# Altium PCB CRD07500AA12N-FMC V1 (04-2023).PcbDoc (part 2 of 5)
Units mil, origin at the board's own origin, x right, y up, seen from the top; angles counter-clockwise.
Board outline 8000 x 8000 mil, 4 copper layers (Top Layer, Layer 1, Layer 2, Bottom Layer), stack 107.988 mil thick; 393 components, 213 nets, 1142 pads, 380 vias.
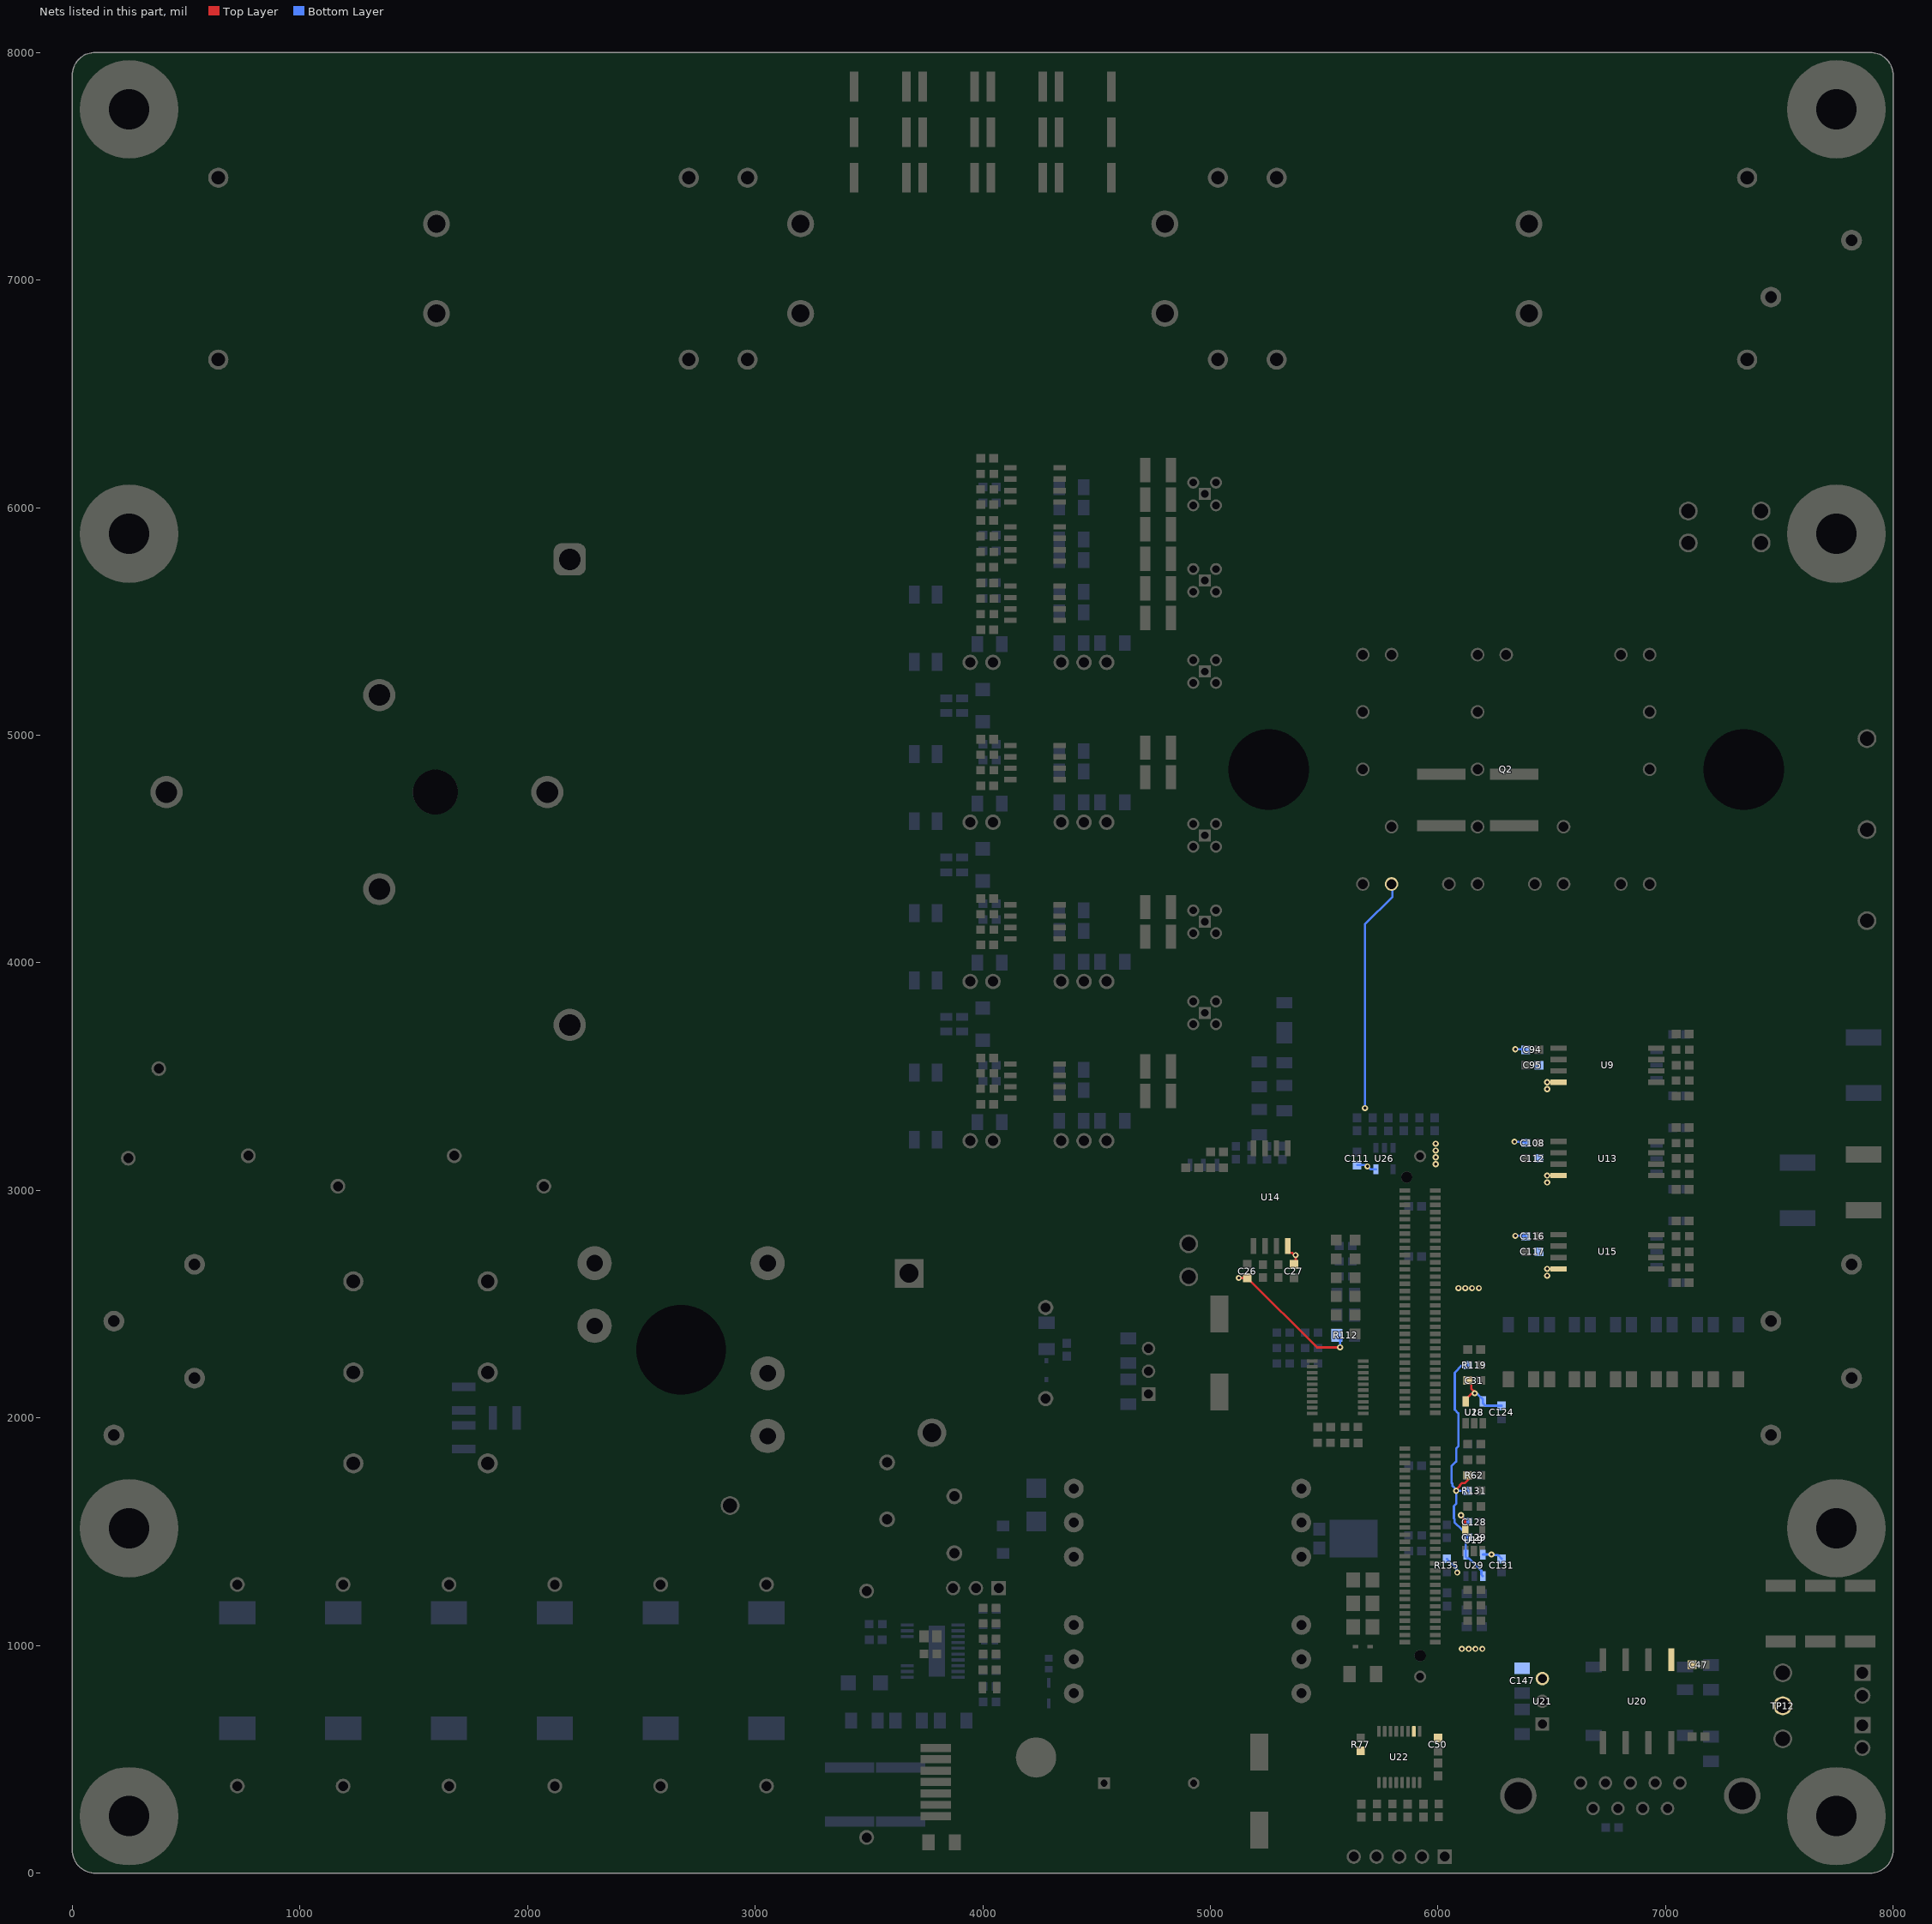
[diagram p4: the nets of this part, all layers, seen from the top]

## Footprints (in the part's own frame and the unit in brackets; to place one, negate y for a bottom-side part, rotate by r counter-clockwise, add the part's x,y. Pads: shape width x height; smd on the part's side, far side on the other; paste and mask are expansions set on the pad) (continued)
SMBJSeries_LTF [mil]
  rect 86x86 smd paste+0 mask+0: 1(-73,0) 2(73,0)
  silkscreen extent -180,-82 115,82, body extent -110,-77 110,77, height 98
SOD323_DIO [mm]
  rect 1.111x0.401 smd paste+0 mask+0: 1(-1.15,0) 2(1.15,0)
  silkscreen extent -1.03,-0.83 1.03,0.83, body extent -1.35,-0.7 1.35,0.7, height 0.81
SOT-89_4P5X2P45_DIO [mil]
  rect 21x55 smd paste+0 mask+0: 1(-59.06,-64) 2(0,-64) 3(59.06,-64)
  Top Layer region: 10.5,-48 -10.5,-48 -10.5,-27.5 -31.5,-7.5 -31.5,97.5 -16.25,97.5 16.25,97.5 31.5,97.5 31.5,-7.5 10.5,-27.5
  silkscreen extent -104,-88 94,53, body extent -92,-89 92,87, height 67
SOT_20100V_ONS [mil]
  rect 57x53 smd paste+0 mask+0: 1(41.34,-112.5) 2(-41.34,-112.5)
  rect 165x211 smd paste+0 mask+0: 3(0,39.5)
  silkscreen extent -97,-126 97,241, body extent -91,-131 91,131, height 49
TECO-640456-2_V [mm] "HDR, 2-Leads, Body 5.715x5.08mm, Pitch 2.54mm"
  rect 1.8x1.8 hole 1.3: 1(1.27,0)
  round 1.8 hole 1.3: 2(-1.27,0)
  silkscreen extent -2.54,-2.54 3.26,3.17, body extent -2.54,-2.67 2.54,3.17, height 10.09
TMDSCNCD280039C [mm]
  rect 0.5x1.2 smd paste+0 mask+0: 1(25.2,1.7) 2(25.2,-1.7) 3(24.4,1.7) 4(24.4,-1.7) 5(23.6,1.7) 6(23.6,-1.7) 7(22.8,1.7) 8(22.8,-1.7) 9(22,1.7) 10(22,-1.7) 11(21.2,1.7) 12(21.2,-1.7) 13(20.4,1.7) 14(20.4,-1.7) 15(19.6,1.7) 16(19.6,-1.7) 17(18.8,1.7) 18(18.8,-1.7) 19(18,1.7) 20(18,-1.7) 21(17.2,1.7) 22(17.2,-1.7) 23(16.4,1.7) 24(16.4,-1.7) 25(15.6,1.7) 26(15.6,-1.7) 27(14.8,1.7) 28(14.8,-1.7) 29(14,1.7) 30(14,-1.7) 31(13.2,1.7) 32(13.2,-1.7) 33(12.4,1.7) 34(12.4,-1.7) 35(11.6,1.7) 36(11.6,-1.7) 37(10.8,1.7) 38(10.8,-1.7) 39(10,1.7) 40(10,-1.7) 41(9.2,1.7) 42(9.2,-1.7) 43(8.4,1.7) 44(8.4,-1.7) 45(7.6,1.7) 46(7.6,-1.7) 47(6.8,1.7) 48(6.8,-1.7) 49(6,1.7) 50(6,-1.7) 51(5.2,1.7) 52(5.2,-1.7) 53(4.4,1.7) 54(4.4,-1.7) 55(3.6,1.7) 56(3.6,-1.7) 57(-0.4,1.7) 58(-0.4,-1.7) 59(-1.2,1.7) 60(-1.2,-1.7) 61(-2,1.7) 62(-2,-1.7) 63(-2.8,1.7) 64(-2.8,-1.7) 65(-3.6,1.7) 66(-3.6,-1.7) 67(-4.4,1.7) 68(-4.4,-1.7) 69(-5.2,1.7) 70(-5.2,-1.7) 71(-6,1.7) 72(-6,-1.7) 73(-6.8,1.7) 74(-6.8,-1.7) 75(-7.6,1.7) 76(-7.6,-1.7) 77(-8.4,1.7) 78(-8.4,-1.7) 79(-9.2,1.7) 80(-9.2,-1.7) 81(-10,1.7) 82(-10,-1.7) 83(-10.8,1.7) 84(-10.8,-1.7) 85(-11.6,1.7) 86(-11.6,-1.7) 87(-12.4,1.7) 88(-12.4,-1.7) 89(-13.2,1.7) 90(-13.2,-1.7) 91(-14,1.7) 92(-14,-1.7) 93(-14.8,1.7) 94(-14.8,-1.7) 95(-15.6,1.7) 96(-15.6,-1.7) 97(-16.4,1.7) 98(-16.4,-1.7) 99(-17.2,1.7) 100(-17.2,-1.7) 101(-18,1.7) 102(-18,-1.7) 103(-18.8,1.7) 104(-18.8,-1.7) 105(-19.6,1.7) 106(-19.6,-1.7) 107(-20.4,1.7) 108(-20.4,-1.7) 109(-21.2,1.7) 110(-21.2,-1.7) 111(-22,1.7) 112(-22,-1.7) 113(-22.8,1.7) 114(-22.8,-1.7) 115(-23.6,1.7) 116(-23.6,-1.7) 117(-24.4,1.7) 118(-24.4,-1.7) 119(-25.2,1.7) 120(-25.2,-1.7)
  round 1.34 hole 0.84 paste-1000 mask+0: 121(-29.05,0) 122(29.05,0)
  round 1.27 hole 1.27 unplated paste-1000 mask+0: ""(-26.7,-1.5) ""(26.7,0)
  silkscreen extent -33.55,-4.25 33.55,3.56, body extent -33.87,-4.89 34.67,5.68, height 57.35
TSSOP20_FE_BB(16) [mm]
  rect 1.461x0.351 smd paste+0 mask+0: 1(-2.825,2.925) 2(-2.825,2.275) 3(-2.825,1.625) 8(-2.825,-1.625) 9(-2.825,-2.275) 10(-2.825,-2.925) 11(2.825,-2.925) 12(2.825,-2.275) 13(2.825,-1.625) 14(2.825,-0.975) 15(2.825,-0.325) 16(2.825,0.325) 17(2.825,0.975) 18(2.825,1.625) 19(2.825,2.275) 20(2.825,2.925)
  rect 1.78x5.68 smd paste-2.827 mask+0: EPAD(0.47,0)
  silkscreen extent -4.06,-3.38 4.06,3.38, body extent -3.2,-3.3 3.2,3.3, height 1.2
WCAP-FTDB_L32W9H18 [mm] "Film Capacitor, THT, body 32.00x9.00mm"
  round 1.65 hole 1.1: 1(-13.75,0) 2(13.75,0)
  silkscreen extent -16.5,-5 16.5,5, body extent -16,-4.5 16,4.5, height 18
WCAP-FTDB_L57W45H65 [mm] "Film Capacitor, THT, body 57.00x45.00mm"
  round 2.25 hole 1.5: 1(-26.25,-10.15) 1(-26.25,10.15) 2(26.25,-10.15) 2(26.25,10.15)
  silkscreen extent -29,-23 29,23, body extent -28.5,-22.5 28.5,22.5, height 65
WCAP-FTXX_L26W11H20_CS [mm] "Film Capacitors, 26x11x20mm"
  round 1.65 hole 1.1: 1(-11.25,0) 2(11.25,0)
  silkscreen extent -13.25,-5.75 13.25,5.75, body extent -13,-5.5 13,5.5, height 20.05
WE-SL2 [mm] "SMD Inductor, 4-Leads, Body 6.3 x 9.5 mm"
  rect 2x1.2 smd: 1(-3.75,1.27) 2(-3.75,-1.27) 3(3.75,-1.27) 4(3.75,1.27)
  silkscreen extent -4.7,-3.18 4.7,3.18, body extent -4.6,-3 4.6,3, height 5
"WE-TPB HV_Type 4XL_744839047160" [mm] "Three-Phase Common Mode Power Line Choke, 6-Leads, body diameter 70mm"
  rrect50% 3.6x3.6 hole 2.4: 1(15,25.981)
  round 3.6 hole 2.4: 2(15,-25.981) 3(-30,0) 4(12.5,0) 5(-6.25,-10.825) 6(-6.25,10.825)
  round 5 hole 5 unplated: MH1(0,0)
  silkscreen extent -35,-35 35,35, body extent -34,-31.29 31.35,30.7, height 37.6

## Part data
C1 C2 C3 C4 C5 C6 C7 C10 C11 C12 C14 C17 C33: "CAP CER 56PF 50V C0G/NP0 0603", Capacitance=56pF, Case Code (Imperial)=0603, Case Code (Metric)=1608, Dielectric=C0G, Manufacturer=SAMSUNG, Max Operating Temperature=125°C, Min Operating Temperature=-55°C, Package Quantity=1, Temperature Coefficient=30ppm/°C, Tolerance=5%, Voltage=50V
C8 C9: "CAP FILM 2200PF 10% 1KVDC 2220", Capacitance=2.2nF, Case Code (Imperial)=2220, Case Code (Metric)=5750, Dielectric Material=Polyester, Manufacturer=KEMET, Max Operating Temperature=125°C, Min Operating Temperature=-55°C, Ratings=AEC-Q200, Tolerance=10%, Voltage Rating=1kV, Voltage Rating (AC)=250V
C13 C18 C19 C24 C26 C94 C108 C117 C143: "CAP CER 4.7UF 25V X5R 0603", Capacitance=4.7µF, Case Code (Imperial)=0603, Case Code (Metric)=1608, Dielectric=X5R, Manufacturer=SAMSUNG, Max Operating Temperature=85°C, Min Operating Temperature=-55°C, Package Quantity=1, Tolerance=20%, Voltage Rating=25V
C15 C20 C25 C110 C130: "CAP CER 4700PF 25V 10% X7R 0603", Capacitance=4.7nF, Case Code (Imperial)=0603, Case Code (Metric)=1608, Dielectric=X7R, Dielectric Material=Ceramic, Manufacturer=KEMET, Manufacturer Part Number=C0603C472K3RACTU, Max Operating Temperature=125°C, Min Operating Temperature=-55°C, Package Quantity=1, Supplier Part Number 1=67AH9250, Tolerance=10%, Voltage Rating=25V
C16 C22 C23 C27 C28 C95 C100 C109 C112 C113 C116: library part CMP-2006-03057-2, "CAP CER 0.1UF 25V X7R 0603", Capacitance=0.1μF, Manufacturer=KEMET, Package=0603, Temperature="-55°C to +125°C", Temperature Characteristic=X7R, Temperature Coefficient=30ppm/°C, Temperature Range High=+125°C, Temperature Range Low=-55°C, Tolerance=0.1, Voltage Rating=25V
C21 C93 C107 C115: "CAP CER 0.33UF 50V X7R 0603", Capacitance=330nF, Case Code (Imperial)=0603, Case Code (Metric)=1608, Dielectric=X7R, Dielectric Material=Ceramic, Manufacturer=TDK, Max Operating Temperature=125°C, Min Operating Temperature=-55°C, Package Quantity=1, Supplier Part Number 1=81AC7913, Tolerance=10%, Voltage=50V
C29 C51: library part CMP-05428-000644-1, "CAP ALUM POLY 470UF 20% 25V SMD", Capacitance=470μF, Case/Package=Radial, ESR (Equivalent Series Resistance)=20mR, Manufacturer=PANASONIC, Manufacturer Part Number=EEH-ZK1E471P, Max Operating Temperature=125°C, Min Operating Temperature=-55°C, Package=RADIAL, Ratings=AEC-Q200, Resistor Type=Hybrid, Tolerance=20%, Voltage Rating=25V
C30 C34 C35 C122 C125 C127: "CAP CER 10000PF 25V X7R 0603", Capacitance=10nF, Case Code (Imperial)=0603, Case Code (Metric)=1608, Manufacturer=SAMSUNG, Max Operating Temperature=125°C, Min Operating Temperature=-55°C, Ratings=AEC-Q200, Tolerance=10%, Voltage Rating=25V
C31: library part CMP-2006-03057-2, "CAP CER 0.1UF 25V X7R 0603", Capacitance=0.10μF, Manufacturer=KEMET, Package=0603, Temperature="-55°C to +125°C", Temperature Characteristic=X7R, Temperature Coefficient=30ppm/°C, Temperature Range High=+125°C, Temperature Range Low=-55°C, Tolerance=0.1, Voltage Rating="25 V"
C32 C65 C66 C68 C70 C72 C74 C79 C81 C86 C88 C96 C98: "CAP CER 2.2UF 50V X5R 0603", Capacitance=2.2μF, Case Code (Imperial)=0603, Case Code (Metric)=1608, Manufacturer=MURATA, Max Operating Temperature=85°C, Min Operating Temperature=-55°C, Ratings=AEC-Q200, Tolerance=20%, Voltage Rating=50V
C36: "WCAP-FTDB DC-LINK CAPACITOR (MKP", Capacitance=1µF, Insulation Resistance=10GΩ, Manufacturer=WURTH, Operating Temperature Max=105°C, Operating Temperature Min=-40°C, Package=N/A, Rate of Voltage Rise=70V/µs, Rated Voltage (DC)=900V, Supplier Part Number 1=710-890724427001CS
C37 C38 C39 C40 C41 C42: "CAP FILM 1UF 10% 310VAC RADIAL", Capacitance=1µF, Dielectric=PP, Manufacturer=WURTH, Max Operating Temperature=105°C, Min Operating Temperature=-40°C, Package=RADIAL, Ratings=X2, Supplier Part Number 1=93X5080, Tolerance=10%, Voltage Rating (AC)=310V
C43 C44 C45: library part CMP-08246-006112-1, "CAP CER 33UF 25V JB 1206", Capacitance=33μF, Case Code (Imperial)=1206, Case Code (Metric)=3216, Dielectric Material=Ceramic, Manufacturer=TDK, Max Operating Temperature=85°C, Min Operating Temperature=-25°C, Package Quantity=2000, Tolerance=20%, Voltage Rating=25V
C46: library part CMP-13271-004306-1, "CAP CER 4.7UF 50V X5R 0805", Capacitance=4.7μF, Case Code (Imperial)=0805, Case Code (Metric)=2012, Dielectric=X5R, Manufacturer=SAMSUNG, Max Operating Temperature=85°C, Min Operating Temperature=-55°C, Package Quantity=1, Tolerance=10%, Voltage Rating=50V
C47 C49 C50 C52 C105 C111 C114 C118 C119 C121 C124 C126 C128 C129 C131 C133 C141: library part CMP-2006-03057-2, "CAP CER 0.1UF 25V X7R 0603", Capacitance=0.10μF, Manufacturer=KEMET, Package=0603, Temperature="-55°C to +125°C", Temperature Characteristic=X7R, Temperature Coefficient=30ppm/°C, Temperature Range High=+125°C, Temperature Range Low=-55°C, Tolerance=0.1, Voltage Rating=25V
C48 C54 C55 C56 C148: library part CMP-2006-03341-2, "CAP CER 1000PF 100V C0G/NP0 0603", Capacitance=1nF, Manufacturer=KEMET, Package=0603, Temperature="-55°C to +125°C", Temperature Characteristic=C0G, Temperature Coefficient=30ppm/°C, Temperature Range High=+125°C, Temperature Range Low=-55°C, Tolerance=0.05, Voltage Rating=100V
C53: library part CMP-02417-000069-1, "CAP CER 2200PF 760VAC Y5U RADIAL", Capacitance=2.2nF, Case/Package=Radial, Dielectric=Y5U, Manufacturer=VISHAY, Max Operating Temperature=125°C, Min Operating Temperature=-40°C, Package=RADIAL, Package Quantity=500, Ratings=X1, Resistor Type=Ceramic, Tolerance=20%, Voltage=500V, Voltage Rating (AC)=760V
C57 C58 C59: library part 890724429010CS, "WCAP-FTDB DC-LINK CAPACITOR (MKP", Capacitance=75µF, Insulation Resistance=133.33MΩ, Manufacturer=WURTH, Operating Temperature Max=105°C, Operating Temperature Min=-40°C, Package=N/A, Rate of Voltage Rise=15V/µs, Rated Voltage (DC)=900V
C60 C61 C62 C63: "CAP ALUM 1200UF 20% 400V SNAP", Capacitance=1.2mF, Case/Package=Radial, ESR (Equivalent Series Resistance)=100mR, Manufacturer=TDK, Max Operating Temperature=85°C, Min Operating Temperature=-25°C, Package=N/A, Supplier Part Number 1=16AC3142, Tolerance=20%, Voltage Rating=400V
C64 C67 C69 C71 C73 C75 C76 C77 C78 C80 C82 C83 C84 C85 C87 C89 C90 C91 C92 C97 C99 C101 C102 C106 C120 C123 C146 C147 C149 C150: library part CMP-13271-001434-1, "CAP CER 10UF 25V X7R 1206", Capacitance=10μF, Case Code (Imperial)=1206, Case Code (Metric)=3216, Dielectric=X7R, Manufacturer=SAMSUNG, Max Operating Temperature=125°C, Min Operating Temperature=-55°C, Package Quantity=1, Tolerance=10%, Voltage Rating=25V
C103: "CAP CER 0.56UF 10V X5R 0603", Capacitance=560nF, Case Code (Imperial)=0603, Case Code (Metric)=1608, Dielectric=X5R, Dielectric Material=Ceramic, Manufacturer=KEMET, Max Operating Temperature=85°C, Min Operating Temperature=-55°C, Package Quantity=4000, Supplier Part Number 1=67AC7992, Tolerance=10%, Voltage=10V
C104: "CAP CER 1UF 10V X7R 0603", Capacitance=1μF, Case Code (Imperial)=0603, Case Code (Metric)=1608, Dielectric=X7R, Dielectric Material=Ceramic, Manufacturer=KEMET, Max Operating Temperature=125°C, Min Operating Temperature=-55°C, Package Quantity=1, Supplier Part Number 1=76Y2906, Tolerance=10%, Voltage Rating=10V
C132 C140 C142: "CAP CER 2200PF 50V X7R 0603", Capacitance=2.2nF, Case Code (Imperial)=0603, Case Code (Metric)=1608, Dielectric=X7R, Manufacturer=TDK, Max Operating Temperature=125°C, Min Operating Temperature=-55°C, Package Quantity=1, Ratings=AEC-Q200, Resistor Type=Ceramic, Supplier Part Number 1=25AC6862, Tolerance=10%, Voltage Rating=50V
C134 C135 C136 C137 C138 C139: "SMDY1 X760Y500VAC 1500PF 20% Y5U", Manufacturer=VISHAY, Package=2-SMD, Supplier Part Number 1=594-SMDY1152MY5UCR, Voltage=760V
C144 C145: library part CMP-2006-03416-2, "CAP CER 47PF 100V 10% NP0 0603", Capacitance=47pF, Manufacturer=KEMET, Package=0603, Temperature="-55°C to +125°C", Temperature Characteristic=C0G, Temperature Coefficient=30ppm/°C, Temperature Range High=+125°C, Temperature Range Low=-55°C, Tolerance=0.1, Voltage Rating=100V
C151 C152: library part CMP-08246-006150-1, "CAP CER 10000PF 2KV X7S 2220", Capacitance=10nF, Case Code (Imperial)=2220, Case Code (Metric)=5750, Dielectric=X7S, Manufacturer=TDK, Max Operating Temperature=125°C, Min Operating Temperature=-55°C, Package Quantity=1, Resistor Type=Ceramic, Tolerance=10%, Voltage Rating=2kV
D1: "BRIDGE RECT 3P 1.2KV 25A", Manufacturer="MULTICOMP PRO", Package=N/A
D2 D5 D6 D7: library part CMP-22017-000007-1, "LED GREEN CLEAR CHIP SMD", Case Code (Imperial)=0805, Case Code (Metric)=2012, Color=GREEN, Forward Current=30mA, Forward Voltage=2.1V, Illumination Color=Green, Lens Color=Colorless, Manufacturer=LITE-ON, Max Operating Temperature=85°C, Min Operating Temperature=-55°C, Package Quantity=1, Power Dissipation=100mW, Reverse Voltage=5V, Test Current=10mA
D3: "LED YELLOW CLEAR 0805 SMD", Case Code (Imperial)=0805, Case Code (Metric)=2012, Color=Yellow, Color Print=YELLOW, Forward Current=30mA, Forward Voltage=2V, Lens Color=Colorless, Manufacturer=LITE-ON, Max Operating Temperature=85°C, Max Power Dissipation=75mW, Min Operating Temperature=-55°C, Package Quantity=1, Reverse Voltage=5V, Supplier Part Number 1=6920950, Test Current=20mA
D4: "LED RED DIFFUSED 0805 SMD", Case Code (Imperial)=0805, Case Code (Metric)=2012, Color=RED, Forward Current=20mA, Forward Voltage=2V, Illumination Color=Red, Manufacturer="VISUAL COMMUNICATIONS", Max Operating Temperature=85°C, Min Operating Temperature=-40°C, Package Quantity=1, Power Rating=100mW, Reverse Voltage=5V, Supplier Part Number 1=45X6246
D8: "DIODE ZENER 13V 300MW SOD523", Manufacturer=CENTRAL, Max Operating Temperature=150°C, Max Power Dissipation=300mW, Min Operating Temperature=-65°C, Package=SOD-523, Supplier Part Number 1=1514-CMOZ13VTRPBFREECT-ND, Tolerance=5%, Zener Voltage=13V
D9 D10 D11: "3.2X1.6MM Purple SMD Led (X=0.19, Y=0.05), Rohs", Color=PURPLE, Manufacturer=Kingbright, Manufacturer Print=KINGBRIGHT, Supplier Part Number 1=604-APTR3216-VFX
D12: library part CMP-1667-00004-1, "DIODE GEN PURP 75V 150MA SOD323", Manufacturer="DIODES INC", Package=SOD-323
D13: "TVS DIODE 188VWM DO214AA", Breakdown Voltage=209V, Clamping Voltage=328V, Manufacturer=LITTELFUSE, Max Operating Temperature=150°C, Max Surge Current=2A, Mfr_Name="Littelfuse Inc", Min Operating Temperature=-55°C, Operating Supply Voltage=188V, Package=DO-214AA, Package Quantity=3000, Peak Pulse Power=600W, Power Line Protection=No, Resistor Type=Zener, Supplier Part Number 1=18-SMBJ188ACT-ND
D14: "DIODE SCHOTTKY 120V 20A TO277-3", Average Rectified Current=20A, Manufacturer=ONSEMI, Max Forward Surge Current (Ifsm)=270A, Max Repetitive Reverse Voltage (Vrrm)=120V, Package=TO-277-3
D15: "DIODE GEN PURP 1KV 1A SOD123FA", Capacitance=15pF, Forward Current=1A, Manufacturer=ONSEMI, Max Junction Temp=+150°C, Max Repetitive Reverse Voltage=1000V, Max Surge Forward Current=30A, Package=SOD-123W, Peak Reverse Current=5uA, Temperature="-55°C to +150°C", Temperature Range Low=-55°C
D16: "DIODE ZENER 220V 1.25W DO214AC", Manufacturer=VISHAY, Max Power Dissipation=1.25W, Package=DO-214AC, Tolerance=5.68%, Zener Voltage=220V
D17: "DIODE GEN PURP 150V 200MA SOD323", Average Rectified Current=200mA, Capacitance=5pF, Forward Voltage=1.25V, Manufacturer="DIODES INC", Max Forward Surge Current (Ifsm)=2.5A, Max Operating Temperature=150°C, Max Repetitive Reverse Voltage (Vrrm)=200V, Max Reverse Current=100nA, Max Reverse Voltage (DC)=150V, Mfr_Name="Diodes Inc", Min Operating Temperature=-65°C, Package=SOD-323, Package Quantity=3000, Power Dissipation=200mW, Supplier Part Number 1=4063921
F1 F2 F3: library part CMP-1502-00235-1, "FUSEHOLDER BLOCKS - PCB - CLIP C", Manufacturer=WURTH, Operating Temperature=-30to120degC, Package=N/A
HS1: "HEATSINK EXTRUSION 200MM", Case/Package=200, Manufacturer="HS MARSTON", Natural Thermal Resistance=0.7°C/W, Package=N/A, Supplier Part Number 1=526770
J1: "TERM BLK 2P SIDE ENT 6.35MM PCB", Color=Green, Current=30A, Current Rating=41A, Manufacturer="PHOENIX CONTACT", Package=N/A, Package Quantity=50, Supplier Part Number 1=651-1777545, Voltage=600V, Voltage Rating=1kV
J2 J3 J4 J5 J6 J7: "CONN MMCX JACK STR 50 OHM PCB", Manufacturer=MOLEX, Manufacturer Part Number=73415-1471, Max Frequency=6GHz, Operating Frequency=N/A, Package Quantity=500, Supplier Part Number 1=70364031
J8 J9: "TERM BLK 4P SIDE ENT 6.35MM PCB", Color=Green, Current=30A, Current Rating=41A, Manufacturer="PHOENIX CONTACT", Package=N/A, Package Quantity=50, Supplier Part Number 1=651-1777561, Voltage=600V, Voltage Rating=1kV
J10: "CONN HEADER VERT 3POS 2.54MM", Color=Black, Manufacturer=WURTH, Package=N/A, Supplier Part Number 1=20X0950
J11 J12: library part CMP-2000-05417-1, "CONN HEADER VERT 2POS 2.54MM", Color=White, Current, Rating="5 /  / A", Flammability Rating=UL94V-0, Manufacturer=TE, Package=N/A, Temperature, Operating="-55to+105 /  / degC", Voltage, Rating="250 /  / V"
J13: "CONN D-SUB PLUG 9POS R/A SLDR", Color=Black, Current Rating=5A, Manufacturer=AMPHENOL, Max Operating Temperature=155°C, Max Supply Voltage (AC)=250V, Min Operating Temperature=-55°C, Package=N/A, Supplier Part Number 1=70145033
J14: library part CMP-1502-01068-1, "CONN HEADER VERT 5POS 2.54MM", Contact Resistance=20mOhm, Manufacturer=WURTH, Operating Temperature=-40to105degC, Package=N/A, Rated Current=3A, Withstanding Voltage=500VAC, Working Voltage=250VAC
K1: library part CMP-03395-000345-1, "RELAY GEN PURPOSE SPST 30A 12V", Coil Current=75mA, Coil Power=900mW, Coil Resistance=160R, Coil Voltage (DC)=12V, Contact Current Rating=30A, Manufacturer=TE, Max Operating Temperature=105°C, Min Operating Temperature=-40°C, Package=N/A
L1: library part 744839047160, "CMC 47MH 16A 3LN TH", Case/Size Code="Type 4XL", DC Resistance Max=14mΩ, Insulation Test Voltage (AC)=3000V, Manufacturer=WURTH, Operating Temperature Max=125°C, Operating Temperature Min=-40°C, Package=N/A, Rated Current=16A, Rated Voltage (AC)=760V
L2 L3 L4 L5: "CMC 10UH 1.6A 2LN 920 OHM SMD", Case/Package=SMD/SMT, Current=1.6A, DC Resistance (DCR)=80mR, Inductance=10uH, Manufacturer=WURTH, Max Operating Temperature=125°C, Min Operating Temperature=-40°C, Package=N/A, Package Quantity=1, Supplier Part Number 1=9040408, Test Frequency=1kHz, Tolerance=30%, Voltage Rating=80V
MH1 MH2 MH3 MH4: "HEX STANDOFF M4 ALUMINUM 31MM F-F", Manufacturer=MCMASTER-CARR, Manufacturer Part Number=95947A065, Package=N/A
Q1: library part CMP-240936-000109-2, "SICFET N-CH 900V 11A D2PAK-7", Case/Package=TO-263-8, Continuous Drain Current (ID)=11A, Drain to Source Voltage (Vdss)=900V, Input Capacitance=150pF, Manufacturer=WOLFSPEED, Max Operating Temperature=150°C, Max Power Dissipation=50W, Min Operating Temperature=-55°C, Package=TO-263-7, Threshold Voltage=2.1V
Q2: "1200V SIC 6-PACK MODULE", Manufacturer=WOLFSPEED, Package=N/A
R1 R2 R3 R4 R5 R6 R7 R8 R9 R10 R11 R12: "RES 82K OHM 1% 2W 2512", Manufacturer=TE, Package=2512, Power=2W
R13 R17 R21 R25 R29 R35: "RES SMD 0 OHM JUMPER 3/4W 1210", Case Code (Imperial)=1210, Case Code (Metric)=3225, Manufacturer=VISHAY, Max Operating Temperature=155°C, Max Power Dissipation=750mW, Min Operating Temperature=-55°C, Package Quantity=10, Power Rating=0.75W, Resistance=0Ω, Supplier Part Number 1=71-CRCW12100000Z0EAH
R14 R15 R18 R19 R22 R24 R26 R27 R30 R31 R37 R39 R59: "RES SMD 49.9 OHM 1% 1/10W 0603", Case Code (Imperial)=0603, Case Code (Metric)=1608, Manufacturer=PANASONIC, Max Operating Temperature=155°C, Max Power Dissipation=100mW, Min Operating Temperature=-55°C, Package Quantity=5000, Power Rating=0.1W, Resistance=49.9Ω, Resistance Tolerance=1%, Resistor Type="Thick Film", Supplier Part Number 1=12AC1058, Temperature Coefficient=100ppm/°C, Voltage Rating=75V, Voltage Rating (DC)=50V, Working Voltage=6V
R16 R20 R23 R28 R32 R40: library part CMP-2005-02198-1, "RES 0.91 OHM 1% 1W 1210", Manufacturer=VISHAY, Package=1210, Power=1W
R33 R34 R36 R38 R41 R42 R44 R45 R46 R47 R48 R49 R50 R51: "RES 22 OHM 1% 1/10W 0603", Case Code (Imperial)=0603, Case Code (Metric)=1608, Manufacturer=YAGEO, Max Operating Temperature=155°C, Min Operating Temperature=-55°C, Power Rating=0.1W, Resistance=22Ω, Resistor Type="Thick Film", Supplier Part Number 1=3067715, Temperature Coefficient=100ppm/°C, Tolerance=1%, Voltage Rating=50V
R43 R89 R99: "RES 0.002 OHM 1% 3W 2512", Case Code (Imperial)=2512, Case Code (Metric)=6432, Manufacturer=BOURNS, Max Operating Temperature=170°C, Max Power Dissipation=3W, Min Operating Temperature=-55°C, Ratings=AEC-Q200, Resistance=2mΩ, Resistance Tolerance=1%, Resistor Type="Metal Alloy", Supplier Part Number 1=75X1531, Temperature Coefficient=75ppm/°C
R52 R63 R130 R139: "RES 0 OHM JUMPER 1/10W 0603", Case Code (Imperial)=0603, Case Code (Metric)=1608, Current Rating=1A, Manufacturer=YAGEO, Max Operating Temperature=155°C, Max Power Dissipation=100mW, Min Operating Temperature=-55°C, Package Quantity=5000, Power Rating=0.1W, Resistance=0Ω, Resistance Tolerance=1%, Resistor Type="Thick Film", Supplier Part Number 1=2581684, Temperature Coefficient=200ppm/°C, Voltage Rating=50V, Working Voltage=75V
R53 R111 R125: library part CMP-2003-04604-1, "RES 249K OHM 0.1% 1/4W 1206", Manufacturer="VISHAY DALE", Package=1206, Power=0.25W, Resistance=249kΩ
R54 R55 R56 R57 R58 R106 R107 R108 R109 R110 R120 R121 R122 R123 R124: library part CMP-2003-04604-1, "RES 249K OHM 0.1% 1/4W 1206", Manufacturer=VISHAY, Package=1206, Power=0.25W, Resistance=249kΩ
R60 R136 R137: "RES SMD 10K OHM 1% 1/10W 0603", Case Code (Imperial)=0603, Case Code (Metric)=1608, Manufacturer=PANASONIC, Manufacturer Part Number=ERJ-3EKF1002V, Max Operating Temperature=155°C, Max Power Dissipation=0.1W, Min Operating Temperature=-55°C, Package Quantity=1, Power Rating=100mW, Resistance=10kΩ, Resistance Tolerance=1%, Resistor Type="Thick Film", Supplier Part Number 1=1051156, Temperature Coefficient=100ppm/°C, Voltage Rating=75V
R61 R77 R126 R132: "RES 4.99K OHM 1% 1/10W 0603", Case Code (Imperial)=0603, Case Code (Metric)=1608, Manufacturer=YAGEO, Max Operating Temperature=155°C, Max Power Dissipation=0.1W, Min Operating Temperature=-55°C, Package Quantity=1, Resistance=4.99kΩ, Resistance Tolerance=1%, Resistor Type="Thick Film", Supplier Part Number 1=1995595, Temperature Coefficient=100ppm/°C, Voltage Rating=75V, Voltage Rating (DC)=50V
R62 R119 R131: "RES SMD 1.8K OHM 0.1% 1/5W 0603", Case Code (Imperial)=0603, Case Code (Metric)=1608, Manufacturer=PANASONIC, Max Operating Temperature=155°C, Max Power Dissipation=0.2W, Min Operating Temperature=-55°C, Resistance=1.8kΩ, Resistor Type="Thick Film", Temperature Coefficient=50ppm/°C, Tolerance=0.1%
R64 R65 R66: "RES 0 OHM JUMPER 1W 2512", Case Code (Imperial)=2512, Case Code (Metric)=6432, Manufacturer=YAGEO, Max Operating Temperature=155°C, Max Power Dissipation=1W, Min Operating Temperature=-55°C, Package Quantity=4000, Resistance=0Ω, Resistance Tolerance=5%, Resistor Type="Thick Film", Supplier Part Number 1=2465714, Temperature Coefficient=200ppm/°C, Voltage Rating=200V
R67 R68 R70: "RES SMD 20 OHM 0.1% 1/10W 0603", Case Code (Imperial)=0603, Case Code (Metric)=1608, Manufacturer=YAGEO, Max Operating Temperature=125°C, Max Power Dissipation=100mW, Min Operating Temperature=-55°C, Package Quantity=5000, Power Rating=0.1W, Resistance=20Ω, Resistor Type="Thin Film", Supplier Part Number 1=603-RT0603BRD0720RL, Temperature Coefficient=25ppm/°C, Voltage Rating=75V, Voltage Rating (DC)=50V
R69: "RES SMD 121K OHM 1% 1/10W 0603", Case Code (Imperial)=0603, Case Code (Metric)=1608, Manufacturer=YAGEO, Max Operating Temperature=125°C, Max Power Dissipation=100mW, Min Operating Temperature=-55°C, Package Quantity=5000, Power Rating=0.1W, Resistance=121kΩ, Resistor Type="Thin Film", Supplier Part Number 1=2107925, Temperature Coefficient=50ppm/°C, Tolerance=1%, Voltage Rating=75V, Voltage Rating (DC)=50V
R71: "RES 4.53K OHM 1% 1/10W 0603", Case Code (Imperial)=0603, Case Code (Metric)=1608, Manufacturer=YAGEO, Max Operating Temperature=155°C, Max Power Dissipation=100mW, Min Operating Temperature=-55°C, Package Quantity=1, Power Rating=0.1W, Resistance=4.53kΩ, Resistor Type="Thick Film", Supplier Part Number 1=3326097, Temperature Coefficient=100ppm/°C, Tolerance=1%, Voltage Rating=50V
R72: "RES SMD 44.2KOHM 0.1% 1/10W 0603", Case Code (Imperial)=0603, Case Code (Metric)=1608, Manufacturer=YAGEO, Max Operating Temperature=125°C, Max Power Dissipation=0.1W, Min Operating Temperature=-55°C, Package Quantity=5000, Power Rating=100mW, Resistance=44.2kΩ, Resistor Type="Thin Film", Temperature Coefficient=25ppm/°C, Tolerance=0.1%, Voltage Rating=75V, Voltage Rating (DC)=50V
R73 R97: "RES 10 OHM 5% 1/10W 0603", Case Code (Imperial)=0603, Case Code (Metric)=1608, Manufacturer=YAGEO, Max Operating Temperature=155°C, Max Power Dissipation=0.1W, Min Operating Temperature=-55°C, Power Rating=100mW, Resistance=10Ω, Resistance Tolerance=5%, Resistor Type="Thick Film", Supplier Part Number 1=5141098, Temperature Coefficient=200ppm/°C, Voltage Rating=50V
R74: "RES 5.6K OHM 1% 1/10W 0603", Case Code (Imperial)=0603, Case Code (Metric)=1608, Manufacturer=YAGEO, Max Operating Temperature=155°C, Min Operating Temperature=-55°C, Power Rating=0.1W, Resistance=5.6kΩ, Resistor Type="Thick Film", Supplier Part Number 1=13-RC0603FR-135K6LCT-ND, Temperature Coefficient=100ppm/°C, Tolerance=1%, Voltage Rating=50V
R75: "RES SMD 2K OHM 1% 1/4W 1206", Case Code (Imperial)=1206, Case Code (Metric)=3216, Manufacturer=YAGEO, Max Operating Temperature=125°C, Max Power Dissipation=0.25W, Min Operating Temperature=-55°C, Package Quantity=5000, Power Rating=250mW, Resistance=2kΩ, Resistor Type="Thin Film", Temperature Coefficient=50ppm/°C, Tolerance=1%, Voltage Rating=200V
R76: "RES SMD 20 OHM 1% 1/8W 0805", Case Code (Imperial)=0805, Case Code (Metric)=2012, Manufacturer=YAGEO, Max Operating Temperature=125°C, Max Power Dissipation=0.13W, Min Operating Temperature=-55°C, Package Quantity=5000, Power Rating=125mW, Resistance=20Ω, Resistor Type="Thin Film", Supplier Part Number 1=46AK6012, Temperature Coefficient=50ppm/°C, Tolerance=1%, Voltage Rating=150V
R78 R79 R80 R94 R95 R96 R133 R135: "RES SMD 1K OHM 0.5% 1/10W 0603", Case Code (Imperial)=0603, Case Code (Metric)=1608, Manufacturer=YAGEO, Max Operating Temperature=125°C, Max Power Dissipation=100mW, Min Operating Temperature=-55°C, Power Rating=0.1W, Resistance=1kΩ, Resistor Type="Thin Film", Supplier Part Number 1=6012514, Temperature Coefficient=25ppm/°C, Tolerance=0.5%, Voltage Rating=75V, Voltage Rating (DC)=50V
R81: "Res 0.05 Ohm 1.0 W 1% 1206 SMD", Manufacturer=VISHAY, Package=1206, Power=1W
R82 R83 R84 R85 R87 R88: "RES SMD 1K OHM 5% 1/8W 0805", Case Code (Imperial)=0805, Case Code (Metric)=2012, Manufacturer=VISHAY, Max Operating Temperature=155°C, Max Power Dissipation=125mW, Min Operating Temperature=-55°C, Package Quantity=5000, Power Rating=0.13W, Resistance=1kΩ, Resistor Type="Thick Film", Temperature Coefficient=200ppm/°C, Tolerance=5%, Voltage Rating=150V
R86 R90 R91 R92 R93: "THIN FILM RES SMD 68K OHM 0.1% 1", Manufacturer=VISHAY, Package=1206, Power=1W, Resistance=68kΩ, Supplier Part Number 1=71-PHPA1206E6802BST1, Tolerance=0.1%
R98: "RES SMD 20 OHM 0.1% 1/10W 0603", Case Code (Imperial)=0603, Case Code (Metric)=1608, Manufacturer=YAGEO, Max Operating Temperature=125°C, Max Power Dissipation=100mW, Min Operating Temperature=-55°C, Package Quantity=5000, Power Rating=0.1W, Resistance=20Ω, Resistor Type="Thin Film", Supplier Part Number 1=603-RT0603BRD0720RL, Temperature Coefficient=25ppm/°C, Tolerance=0.1%, Voltage Rating=75V, Voltage Rating (DC)=50V
R100 R101 R102: "RES 680 OHM 1% 1/10W 0603", Case Code (Imperial)=0603, Case Code (Metric)=1608, Manufacturer=YAGEO, Max Operating Temperature=155°C, Max Power Dissipation=100mW, Min Operating Temperature=-55°C, Package Quantity=1, Power Rating=0.1W, Resistance=680Ω, Resistance Tolerance=1%, Resistor Type="Thick Film", Supplier Part Number 1=6789788, Temperature Coefficient=100ppm/°C, Voltage Rating=50V
R103: "RES SMD 2K OHM 1% 1/8W 0805", Case Code (Imperial)=0805, Case Code (Metric)=2012, Manufacturer=YAGEO, Max Operating Temperature=125°C, Max Power Dissipation=0.13W, Min Operating Temperature=-55°C, Package Quantity=5000, Power Rating=125mW, Resistance=2kΩ, Resistor Type="Thin Film", Supplier Part Number 1=6100065, Temperature Coefficient=50ppm/°C, Tolerance=1%, Voltage Rating=150V
R104: "RES 499 OHM 1% 1/8W 0805", Case Code (Imperial)=0805, Case Code (Metric)=2012, Manufacturer=YAGEO, Max Operating Temperature=155°C, Max Power Dissipation=0.13W, Min Operating Temperature=-55°C, Package Quantity=1, Power Rating=125mW, Resistance=499Ω, Resistor Type="Thick Film", Supplier Part Number 1=5825161, Temperature Coefficient=100ppm/°C, Tolerance=1%, Voltage Rating=150V
R105: "RES 22 OHM 1% 1/4W 1206", Case Code (Imperial)=1206, Case Code (Metric)=3216, Manufacturer=STACKPOLE, Max Operating Temperature=155°C, Max Power Dissipation=0.3W, Min Operating Temperature=-55°C, Resistance=22Ω, Resistor Type="Thick Film", Temperature Coefficient=100ppm/°C, Tolerance=1%
R112: "RES 249 OHM 1% 1/8W 0805", Case Code (Imperial)=0805, Case Code (Metric)=2012, Manufacturer=YAGEO, Max Operating Temperature=155°C, Max Power Dissipation=125mW, Min Operating Temperature=-55°C, Package Quantity=1, Power Rating=0.13W, Resistance=249Ω, Resistor Type="Thick Film", Supplier Part Number 1=1233097, Temperature Coefficient=100ppm/°C, Tolerance=1%, Voltage Rating=150V
R113 R114 R115 R116 R117 R118: "RES 100K OHM 1% 1/10W 0603", Case Code (Imperial)=0603, Case Code (Metric)=1608, Manufacturer=YAGEO, Max Operating Temperature=155°C, Max Power Dissipation=100mW, Min Operating Temperature=-55°C, Power Rating=0.1W, Resistance=100kΩ, Resistance Tolerance=1%, Resistor Type="Thick Film", Supplier Part Number 1=3697448, Temperature Coefficient=100ppm/°C, Voltage Rating=50V, Working Voltage=75V
R127 R128 R129: "RES SMD 820K OHM 1% 1/3W 1210", Case Code (Imperial)=1210, Case Code (Metric)=3225, Manufacturer=ROHM, Max Operating Temperature=155°C, Max Power Dissipation=0.3W, Min Operating Temperature=-55°C, Package Quantity=4000, Resistance=820kΩ, Resistor Type="Thick Film", Supplier Part Number 1=755-KTR25JZPF8203, Temperature Coefficient=100ppm/°C, Tolerance=1%
R134: "RES 330 OHM 1% 1/10W 0603", Case Code (Imperial)=0603, Case Code (Metric)=1608, Manufacturer=YAGEO, Max Operating Temperature=155°C, Max Power Dissipation=0.1W, Min Operating Temperature=-55°C, Package Quantity=1, Power Rating=100mW, Resistance=330Ω, Resistance Tolerance=1%, Resistor Type="Thick Film", Supplier Part Number 1=2052439, Temperature Coefficient=100ppm/°C, Voltage Rating=50V
R138: "RES SMD 56.2KOHM 0.1% 1/10W 0603", Case Code (Imperial)=0603, Case Code (Metric)=1608, Manufacturer=YAGEO, Max Operating Temperature=125°C, Max Power Dissipation=100mW, Min Operating Temperature=-55°C, Package Quantity=5000, Power Rating=0.1W, Resistance=56.2kΩ, Resistor Type="Thin Film", Supplier Part Number 1=46AK5760, Temperature Coefficient=25ppm/°C, Tolerance=0.1%, Voltage Rating=75V, Voltage Rating (DC)=50V
R140: "RES SMD 100 OHM 1% 1/10W 0603", Case Code (Imperial)=0603, Case Code (Metric)=1608, Manufacturer=YAGEO, Max Operating Temperature=125°C, Max Power Dissipation=100mW, Min Operating Temperature=-55°C, Package Quantity=5000, Power Rating=0.1W, Resistance=100Ω, Resistance Tolerance=1%, Resistor Type="Thin Film", Supplier Part Number 1=4047394, Temperature Coefficient=50ppm/°C, Voltage Rating=75V
R141 R142 R143: "RES SMD 499K OHM 0.5% 1/4W 1206", Case Code (Imperial)=1206, Case Code (Metric)=3216, Manufacturer=YAGEO, Max Operating Temperature=155°C, Max Power Dissipation=0.25W, Min Operating Temperature=-55°C, Package Quantity=5000, Resistance=499kΩ, Resistor Type="Thin Film", Temperature Coefficient=25ppm/°C, Tolerance=0.5%, Voltage Rating (DC)=200V
R144: "RES SMD 120 OHM 5% 1/10W 0603", Case Code (Imperial)=0603, Case Code (Metric)=1608, Manufacturer=YAGEO, Max Operating Temperature=155°C, Max Power Dissipation=0.1W, Min Operating Temperature=-55°C, Package Quantity=1, Power Rating=100mW, Resistance=120Ω, Resistance Tolerance=5%, Resistor Type="Thick Film", Supplier Part Number 1=2424206, Temperature Coefficient=100ppm/°C, Voltage Rating=50V
RV1 RV2 RV3: library part 820525511, "DISK VARISTOR STANDARD WE-VD - B", (Reverse) Breakdown Voltage=910V, (Reverse) Peak Pulse Current=6500A, Channel Input Capacitance=430pF, Clamping Voltage=1500V, Manufacturer=WURTH, Operating Temperature Max=85°C, Operating Temperature Min=-40°C, Operating Voltage (AC)=550V, Operating Voltage (DC)=745V, Package=N/A, Power Dissipation=1W
RV4 RV5: "ICL 5 OHM 20% 20A 31MM", Current Rating=20A, Manufacturer=AMETHERM, Manufacturer Part Number=SL32-5R020-B, Package=N/A, Package Quantity=500, Resistance=5R, Supplier Part Number 1=33K3765, Tolerance=20%
T1: "TRANSFORMER FLYBACK 670UH TH", Manufacturer=SUMIDA, Package=N/A
TP1 TP3 TP8 TP12 TP13: library part CMP-1672-00002-4, "PC TEST POINT MULTIPURPOSE RED", Colour=Red, Manufacturer=KEYSTONE, Package=N/A, Package Quantity=100
TP2 TP4 TP9 TP10 TP11: library part CMP-1672-00003-4, "PC TEST POINT MULTIPURPOSE BLACK", Colour=Black, Manufacturer=KEYSTONE, Package=N/A, Package Quantity=100
TP5 TP6 TP7: library part CMP-1672-00004-4, "PC TEST POINT MULTIPURPOSE WHITE", Colour=White, Manufacturer=KEYSTONE, Package=N/A, Package Quantity=100
U1 U2 U3 U5 U7 U10: "5A/5A, 3-KVRMS SINGLE-CHANNEL IS", Manufacturer="TEXAS INSTRUMENTS", Max Operating Temperature=125°C, Mfr_Name="Texas Instruments", Min Operating Temperature=-40°C, Package=8-SOIC, Supplier Part Number 1=296-47508-ND, Working Voltage=990V
U4 U6 U8 U12: "DC DC CONVERTER 15V -3V 1.7W", Manufacturer=MURATA, Package=7-SIP, Supplier Part Number 1=580-MGJ2D121503SC
U9 U13 U14 U15: "IC ISOLATED MOD 16BIT 78K 8SOIC", Manufacturer="TEXAS INSTRUMENTS", Max Operating Temperature=125°C, Mfr_Name="Texas Instruments", Min Operating Temperature=-40°C, Package=8-SOIC, Supplier Part Number 1=296-50930-1-ND
U11: "EVAL BOARD FOR TMS320F280039C", Manufacturer="TEXAS INSTRUMENTS", Package=N/A, Supplier Part Number 1=595-TMDSCNCD280039C
U16: "DC DC CONVERTER 5V 5W", Case/Package=SIP, Current - Output 1=1A, Manufacturer=RECOM, Max Input Voltage=28V, Max Operating Temperature=85°C, Max Output Voltage=5V, Max Power Dissipation=5W, Min Input Voltage=8V, Min Operating Temperature=-40°C, Package=3-SIP, Package Quantity=42, Supplier Part Number 1=1446013
U17: library part CMP-0440-01163-3, "IC BUF NON-INVERT 5.5V 20TSSOP", F @ Nom Voltage(Max)(Mhz)=110, Generic Part Number=SN74LV541AT, ICC @ Nom Voltage(Max)(mA)=0.02, Manufacturer="TEXAS INSTRUMENTS", Operating Temperature Range(C)="-40 to 125", Package=20-TSSOP, Rating=Catalog, tpd @ Nom Voltage(Max)(ns)=7.9, Voltage(Nom)(V)=5
U18 U19 U28: library part CMP-0384-02059-2, "IC OPAMP GP 1 CIRCUIT TSOT23-5", Amplifiers Per Package=1, Generic Part Number=AD8615, Input Bias Current=200fA, Input Offset Voltage=80uV, Manufacturer="ANALOG DEVICES", Package=TSOT-23-5
U20: "IC TXRX/ISO HALF 1/1 8SOP", Drivers Per Package=1, Manufacturer="TEXAS INSTRUMENTS", Package=8-SOP, Rating=Catalog
U21: "DC DC CONVERTER 3.3V 3W", Case/Package=SIP, Manufacturer=RECOM, Max Input Voltage=28V, Max Operating Temperature=85°C, Max Output Current=1A, Max Output Power=3.3W, Max Output Voltage=3.3V, Max Power Dissipation=3W, Min Input Voltage=8V, Min Input Voltage (DC)=7V, Min Operating Temperature=-40°C, Package=3-SIP, Supplier Part Number 1=9176626
U22: library part CMP-2000-07336-1, "IC TRANSLATOR BIDIR 16TSSOP", Manufacturer="TEXAS INSTRUMENTS", Operating Temperature=-40°C~85°C, Package=16-TSSOP, Package / Case="16-TSSOP(0.173\",4.40mmWidth)", Package Description="16-Pin Small Outline Package Integrated Circuit, Body 5 x 4.4 mm, Pitch 0.65 mm", Package Reference=PW16, Standard Package=1, Voltage - Supply=1.2V~3.6V,1.65V~5.5V
U23 U24 U25 U27: "IC REG LINEAR 5V 100MA SOT89-3", Case/Package=SOT-89-3, Dropout Voltage=1.8V, Manufacturer="DIODES INC", Max Input Voltage=30V, Max Operating Temperature=125°C, Max Output Current=100mA, Max Power Dissipation=750mW, Min Operating Temperature=-40°C, Output Voltage=5V, Package=TO-243AA, Package Quantity=1000, Quiescent Current=3mA, Supplier Part Number 1=1050402
U26 U29: library part CMP-0384-01498-2, "IC OPAMP GP 1 CIRCUIT SOT23-5", Amplifiers Per Package=1, Generic Part Number=AD8541, Input Bias Current=4pA, Input Offset Voltage=1mV, Manufacturer="ANALOG DEVICES", Package=SOT-23-5
U30: "600VIN MICROPOWER, ISOLATED NO-O", Manufacturer="ANALOG DEVICES", Package=20-TSSOP
U31: library part CMP-29842-000014-1, "DC DC CONVERTER 5V 1W", Case/Package=SMD/SMT, Current - Output 1=200mA, Isolation Voltage=1kV, Manufacturer=RECOM, Max Input Voltage=5.5V, Max Operating Temperature=85°C, Max Output Power=1W, Max Output Voltage=5V, Min Input Voltage=4.5V, Min Operating Temperature=-40°C, Package=8-SMD, Package Quantity=1

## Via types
v1: diameter 27, hole 13, Top Layer to Bottom Layer, tented both sides, 367 vias
v2: diameter 50, hole 28, Top Layer to Bottom Layer, tented both sides, 13 vias

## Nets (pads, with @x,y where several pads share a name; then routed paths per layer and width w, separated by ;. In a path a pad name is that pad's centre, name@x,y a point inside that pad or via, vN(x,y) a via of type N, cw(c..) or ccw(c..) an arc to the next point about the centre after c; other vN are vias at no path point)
+1.65V: C129.1 R62.2 R119.2 R131.2 U29.1 U29.4 | length 1217.2
  Top Layer w10: v1(6080,1680) 6080,1684.6 6096.61,1701.21 6096.61,1705.08 6105.4,1713.86 6118.86,1713.86 6135,1730 6135,1744.38 R62.2@6131.38,1748
  Bottom Layer w10: v1@6082.35,1682.35 6084.69,1680 R131.2@6131.38,1680 ; R119.2@6131.38,2232 6129.38,2230 6105,2230 6073.82,2198.82 6073.82,2036.09 6090,2019.91 6090,1875 6080,1865 6080,1808.67 6060.52,1789.19 6060.52,1714.48 6063.81,1711.19 6063.81,1700.79 6080,1684.6 v1(6080,1680) 6080,1622.58 6070,1612.58 6070,1558.65 6072.96,1555.7 6072.96,1541.58 6105.4,1509.14 6115.86,1509.14 6122,1503 6122,1484.43 C129.1@6131.42,1475 6122.6,1466.18 U29.4@6122.6,1399.24 6122.6,1389.4 6129.41,1382.59 6136.84,1382.59 6190.59,1328.84 6190.59,1311.57 U29.1@6197.4,1304.76
+3.3V: C26.1 C27.1 C31.1 C47.1 C50.1 C94.1 C95.1 C108.1 C111.1 C112.1 C116.1 C117.1 C124.1 C128.1 C131.1 C147.1 Q2.NTC1 R77.2 R112.2 R135.2 TP12.1 U9.8 U13.8 U14.8 U15.8 U18.5 U19.5 U20.1 U21.3 U22.2 U26.5 U28.5 U29.5 | length 2596
  Top Layer w10: v1(5125,2615) 5161.58,2615 C26.1@5163,2616.42 5163,2615.47 5468.47,2310 5565,2310 v1@5570,2305 ; U14.8@5340,2755.43 5340,2731.81 5346.81,2725 5360.4,2725 5370.4,2715 v1(5375,2715) 5375,2681.58 C27.1@5367,2673.58 C27.1@5367,2674.53 ; C50.1@5998.58,595 C50.1@6000,593.58 ; v1(6101.51,1572.28) 6101.51,1567.68 6119.15,1550.04 U19.5@6119.15,1511.4 ; U18.5@6122.6,2073.23 6122.6,2082.09 6145.63,2105.12 6158.37,2105.12 v1(6161.63,2108.37) 6161.63,2112.97 6146.24,2128.36 6146.24,2150.14 6132.37,2164 C31.1@6131.42,2164
  Bottom Layer w10: R112.2@5556.54,2358.98 R112.2@5556.54,2363 R112.2@5575,2344.54 ; R112.2@5565,2350 5570,2345 v1(5570,2310) ; C111.1@5645,3111.42 5678.98,3111.42 5685.4,3105 v1(5690,3105) 5691.47,3105 5703.71,3092.76 U26.5@5727.6,3092.76 ; v1(5679.07,3361.11) 5679.07,4169.07 5800,4290 5800,4342.13 Q2.NTC1@5796.06,4346.06 ; R135.2@6040,1380.62 6040,1379.72 6062.48,1357.24 6064.17,1357.24 6081.75,1339.66 6081.75,1323.96 v1(6085,1320.7) ; v1(6101.51,1572.28) 6101.51,1571.97 6130.47,1543 C128.1@6131.42,1543 ; C128.1@6130.47,1535 C128.1@6131.42,1535 ; v1(6161.63,2108.37) 6164.88,2105.12 6174.37,2105.12 6197.4,2082.09 U28.5@6197.4,2073.23 6197.4,2064.37 6208.19,2053.58 C124.1@6280,2053.58 ; U29.5@6197.4,1399.24 6198.16,1400 v1(6235,1400) 6237.92,1397.08 6263.5,1397.08 6265.19,1395.39 6266.14,1395.39 6280,1381.53 C131.1@6280,1380.58 ; v1(6336.25,3213.75) 6380.67,3213.75 C108.1@6386.42,3208 ; v1(6340,2800) 6384.42,2800 C116.1@6386.42,2798 ; v1(6340,3620) 6384.42,3620 C94.1@6386.42,3618
  other v1: 6105,985 6135,985 6165,985 6195,985 6090,2570 6120,2570 6150,2570 6180,2570 6480,2625 6480,2655 6480,3035 6480,3065 5990,3115 5990,3145 5990,3175 5990,3205 6480,3445 6480,3475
